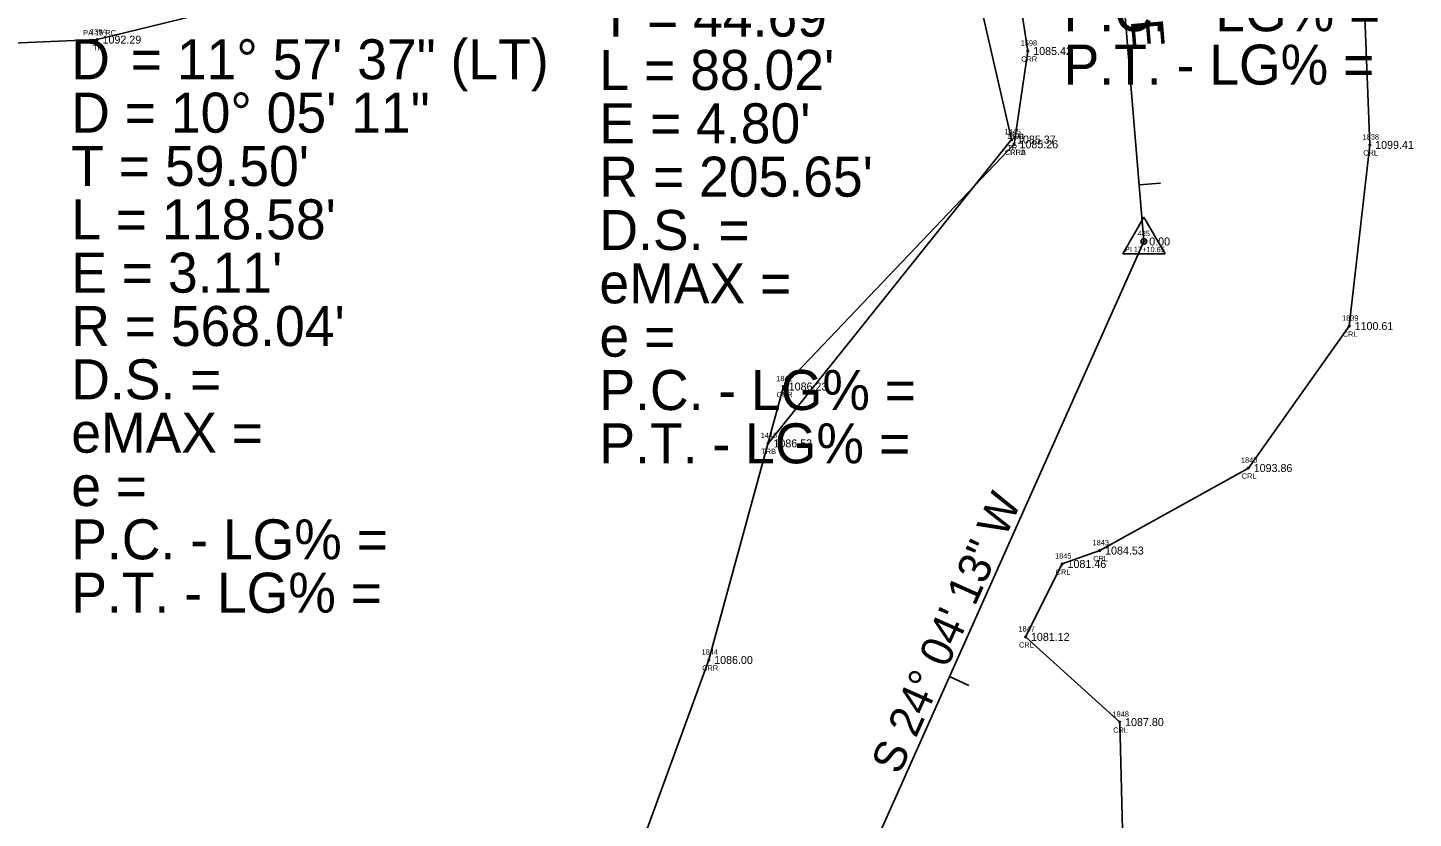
# Model space of a CAD drawing. Extents: x 1539151 to 1541799, y 1198646 to 1201165.
# Drawn here: x 1539950.8 to 1540210.6, y 1199214.5 to 1199362.7 of the extents above; entities that cross this region are included whole.
import ezdxf

# ---------------------------------------------------------------- set-up
doc = ezdxf.new("R2010")
doc.units = 0
for name, color, linetype in [('RD_EX_DR_Pipe_txCode', 7, 'Continuous'), ('RD_EX_H2O', 7, 'Continuous'), ('RD_EX_H2O_txCode', 7, 'Continuous'), ('RD_EX_TX_H2O_ELEV', 7, 'Continuous'), ('RD_EX_TX_VEG_ELEV', 7, 'Continuous'), ('RD_EX_VEG', 7, 'Continuous'), ('RD_EX_VEG_txCode', 7, 'Continuous'), ('RD_HC_Cl', 7, 'Continuous'), ('RD_HC_Data', 7, 'Continuous'), ('RD_HC_Data_Tic', 7, 'Continuous'), ('RD_HC_Survey_ELEV', 7, 'Continuous'), ('RD_HC_txCode', 7, 'Continuous'), ('RD_SMD_Locator', 7, 'Continuous')]:
    doc.layers.add(name, color=color, linetype=linetype)

msp = doc.modelspace()

# ---------------------------------------------------------------- linework, layer by layer
at = {"layer": 'RD_EX_H2O'}
for points in [[(1540167.88, 1199484.64), (1540176.46, 1199458.2), (1540182.66, 1199452.12), (1540193.19, 1199429.05), (1540200.37, 1199393.5), (1540202.4, 1199340.71), (1540198.55, 1199306.73), (1540179.64, 1199280.12), (1540151.78, 1199264.65), (1540144.74, 1199262.14), (1540137.88, 1199248.47), (1540155.53, 1199232.49), (1540156.47, 1199194.6), (1540144.81, 1199166.15), (1540127.69, 1199133.28), (1540119.65, 1199099.79), (1540112.02, 1199051.08), (1540113.69, 1199004.24), (1540113.12, 1198937.28), (1540119.39, 1198871.63)], [(1540110.32, 1199427.56), (1540119.33, 1199416.8), (1540132.83, 1199393.98), (1540138.31, 1199358.3), (1540135.73, 1199340.81)], [(1540135.73, 1199340.81), (1540092.48, 1199295.4), (1540078.51, 1199244.14), (1540063.81, 1199203.89), (1540058.08, 1199149.46), (1540055.34, 1199104.97), (1540048.25, 1199053), (1540041.75, 1198997.25), (1540036.02, 1198924.86), (1540052.85, 1198865.55)]]:
    msp.add_lwpolyline(points, dxfattribs=at)
at = {"layer": 'RD_EX_VEG'}
msp.add_lwpolyline([(1539913.28, 1199258.8), (1539924.81, 1199358.8), (1539963.86, 1199360.44), (1540062.92, 1199384.69), (1540118.75, 1199413.61), (1540135.27, 1199341.7), (1540089.61, 1199284.74)], dxfattribs=at)
at = {"layer": 'RD_HC_Cl'}
for p, q in [((1540150.21, 1199440.05), (1540160.06, 1199322.6)), ((1540160.06, 1199322.6), (1540093.38, 1199173.32))]:
    msp.add_line(p, q, dxfattribs=at)
at = {"layer": 'RD_HC_Data'}
for p, q in [((1540156.09, 1199320.3), (1540160.06, 1199327.18)), ((1540160.06, 1199327.18), (1540164.03, 1199320.3)), ((1540156.09, 1199320.3), (1540164.03, 1199320.3))]:
    msp.add_line(p, q, dxfattribs=at)
msp.add_circle((1540160.06, 1199322.6), 0.529, dxfattribs=at)
at = {"layer": 'RD_HC_Data_Tic'}
for p, q in [((1540159.17, 1199333.21), (1540163.16, 1199333.54)), ((1540123.62, 1199241.01), (1540127.27, 1199239.38))]:
    msp.add_line(p, q, dxfattribs=at)
at = {"layer": 'RD_SMD_Locator'}
for centre in [(1539963.86, 1199360.44), (1540138.31, 1199358.3), (1540135.27, 1199341.7), (1540135.73, 1199340.81), (1540135.73, 1199340.81), (1540202.4, 1199340.71), (1540160.06, 1199322.6), (1540198.55, 1199306.73), (1540092.48, 1199295.4), (1540089.61, 1199284.74), (1540179.64, 1199280.12), (1540151.78, 1199264.65), (1540144.74, 1199262.14), (1540137.88, 1199248.47), (1540078.51, 1199244.14), (1540155.53, 1199232.49)]:
    msp.add_circle(centre, 0.15, dxfattribs=at)

# ---------------------------------------------------------------- texts
at = {"layer": 'RD_EX_DR_Pipe_txCode'}
msp.add_text('PA 15 RC', height=1, dxfattribs=at).set_placement((1539961.24, 1199361.22))
at = {"layer": 'RD_EX_H2O_txCode'}
for s, p in [('1598', (1540136.96, 1199359.3)), ('CRR', (1540137.06, 1199356.3)), ('1599', (1540134.39, 1199341.81)), ('1841', (1540134.67, 1199341.81)), ('1838', (1540201.05, 1199341.71)), ('CRRA', (1540133.99, 1199338.81)), ('CRRB', (1540134.01, 1199338.81)), ('CRL', (1540201.17, 1199338.71)), ('1839', (1540197.2, 1199307.73)), ('CRL', (1540197.32, 1199304.73)), ('1842', (1540091.13, 1199296.4)), ('CRR', (1540091.23, 1199293.4)), ('1840', (1540178.25, 1199281.12)), ('CRL', (1540178.41, 1199278.12)), ('1843', (1540150.43, 1199265.65)), ('1845', (1540143.4, 1199263.14)), ('CRL', (1540150.55, 1199262.65)), ('CRL', (1540143.51, 1199260.14)), ('1847', (1540136.54, 1199249.47)), ('CRL', (1540136.65, 1199246.47)), ('1844', (1540077.16, 1199245.14)), ('CRR', (1540077.26, 1199242.14)), ('1848', (1540154.18, 1199233.49)), ('CRL', (1540154.3, 1199230.49))]:
    msp.add_text(s, height=1, dxfattribs=at).set_placement(p)
at = {"layer": 'RD_EX_TX_H2O_ELEV'}
for s, p in [('1085.42', (1540139.31, 1199357.55)), ('1085.26', (1540136.73, 1199340.06)), ('1085.26', (1540136.73, 1199340.06)), ('1099.41', (1540203.4, 1199339.96)), ('1100.61', (1540199.55, 1199305.98)), ('1086.23', (1540093.48, 1199294.65)), ('1093.86', (1540180.64, 1199279.37)), ('1084.53', (1540152.78, 1199263.9)), ('1081.46', (1540145.74, 1199261.39)), ('1081.12', (1540138.88, 1199247.72)), ('1086.00', (1540079.51, 1199243.39)), ('1087.80', (1540156.53, 1199231.74))]:
    msp.add_text(s, height=1.5, dxfattribs=at).set_placement(p)
at = {"layer": 'RD_EX_TX_VEG_ELEV'}
for s, p in [('1092.29', (1539964.86, 1199359.69)), ('1085.37', (1540136.27, 1199340.95)), ('1086.53', (1540090.61, 1199283.99))]:
    msp.add_text(s, height=1.5, dxfattribs=at).set_placement(p)
at = {"layer": 'RD_EX_VEG_txCode'}
for s, p in [('1394', (1539962.52, 1199361.44)), ('TR', (1539963.07, 1199358.44)), ('1445', (1540133.92, 1199342.7)), ('TR', (1540134.47, 1199339.7)), ('1446', (1540088.24, 1199285.74)), ('TRB', (1540088.34, 1199282.74))]:
    msp.add_text(s, height=1, dxfattribs=at).set_placement(p)
at = {"layer": 'RD_HC_Data'}
for s, rotation, p in [('S 4%%d 47\' 39" E', 274.7943, (1540153.9, 1199408.03)), ('S 24%%d 04\' 13" W', 65.9297, (1540114.22, 1199222.42))]:
    msp.add_text(s, height=6, rotation=rotation, dxfattribs=at).set_placement(p)
for s, p in [('P.C. - LG% = ', (1540145, 1199362)), ("T = 44.69'", (1540058, 1199361)), ('D', (1539959, 1199353)), ('    = 11%%d 57\' 37" (LT)', (1539959, 1199353)), ('P.T. - LG% = ', (1540145, 1199352)), ("L = 88.02'", (1540058, 1199351)), ('D = 10%%d 05\' 11"', (1539959, 1199343)), ("E = 4.80'", (1540058, 1199341)), ("T = 59.50'", (1539959, 1199333)), ("R = 205.65'", (1540058, 1199331)), ("L = 118.58'", (1539959, 1199323)), ('D.S. = ', (1540058, 1199321)), ("E = 3.11'", (1539959, 1199313)), ('eMAX = ', (1540058, 1199311)), ("R = 568.04'", (1539959, 1199303)), ('e = ', (1540058, 1199301)), ('D.S. = ', (1539959, 1199293)), ('P.C. - LG% = ', (1540058, 1199291)), ('eMAX = ', (1539959, 1199283)), ('P.T. - LG% = ', (1540058, 1199281)), ('e = ', (1539959, 1199273)), ('P.C. - LG% = ', (1539959, 1199263)), ('P.T. - LG% = ', (1539959, 1199253))]:
    msp.add_text(s, height=7.5, dxfattribs=at).set_placement(p)
at = {"layer": 'RD_HC_Survey_ELEV'}
msp.add_text('0.00', height=1.5, dxfattribs=at).set_placement((1540161.06, 1199321.85))
at = {"layer": 'RD_HC_txCode'}
for s, p in [('435', (1540158.88, 1199323.6)), ('PI 17+10.65', (1540156.5, 1199320.6))]:
    msp.add_text(s, height=1, dxfattribs=at).set_placement(p)

doc.saveas('drawing.dxf')
